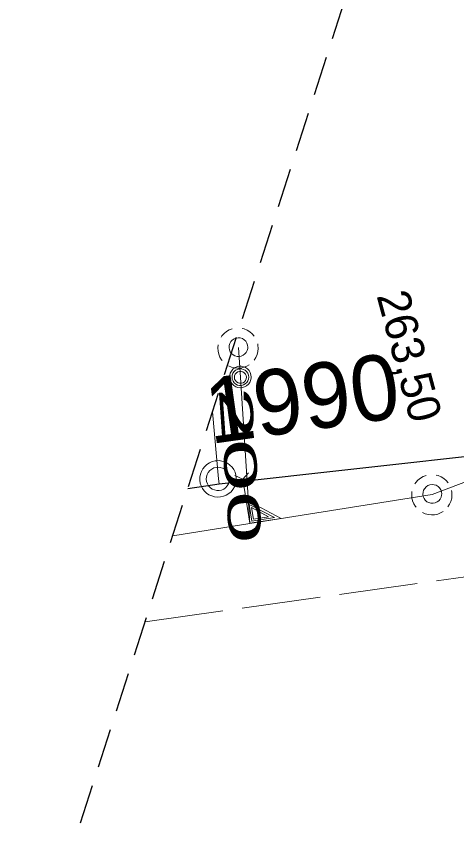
# Model space of a CAD drawing. Extents: x -732074 to -731966, y -1048695 to -1047982.
# Drawn here: x -732050.16 to -732039.39, y -1048256.3 to -1048236.39 of the extents above; entities that cross this region are included whole.
import ezdxf

# ---------------------------------------------------------------- set-up
doc = ezdxf.new("R2010")
doc.units = 0
doc.header["$LTSCALE"] = 0.32
doc.linetypes.add('LONG_DASHED', pattern=[7.5, 6, -1.5])
doc.linetypes.add('MEDIUM_DASHED', pattern=[4.5, 3, -1.5])
doc.layers.add('1', color=7, linetype='Continuous')
for name, color, linetype, lineweight in [('18', 7, 'Continuous', 13), ('20', 7, 'Continuous', 13), ('49', 7, 'Continuous', 13), ('63', 7, 'MEDIUM_DASHED', 25), ('8', 7, 'Continuous', 13)]:
    doc.layers.add(name, color=color, linetype=linetype, lineweight=lineweight)

msp = doc.modelspace()

# ---------------------------------------------------------------- linework, layer by layer
at = {"layer": '18'}
for p, q in [((-732044.481, -1048247.564), (-732044.77, -1048247.883)), ((-732044.814, -1048247.63), (-732044.409, -1048247.813))]:
    msp.add_line(p, q, dxfattribs=at)
for points in [[(-732044.883, -1048244.037), (-732044.954, -1048244.065), (-732045.021, -1048244.104), (-732045.081, -1048244.152), (-732045.132, -1048244.209), (-732045.156, -1048244.243)], [(-732044.342, -1048244.22), (-732044.392, -1048244.162), (-732044.45, -1048244.112), (-732044.515, -1048244.071), (-732044.586, -1048244.042), (-732044.635, -1048244.028)], [(-732045.228, -1048244.429), (-732045.233, -1048244.506), (-732045.228, -1048244.583), (-732045.212, -1048244.658), (-732045.183, -1048244.729), (-732045.142, -1048244.795), (-732045.127, -1048244.817)], [(-732044.347, -1048244.806), (-732044.306, -1048244.741), (-732044.275, -1048244.671), (-732044.255, -1048244.596), (-732044.248, -1048244.52), (-732044.253, -1048244.443), (-732044.259, -1048244.408)], [(-732044.97, -1048244.946), (-732044.9, -1048244.977), (-732044.825, -1048244.996), (-732044.749, -1048245.003), (-732044.672, -1048244.998), (-732044.597, -1048244.981), (-732044.525, -1048244.953), (-732044.465, -1048244.918)], [(-732044.62, -1048247.717), (-732044.447, -1048248.799), (-732043.686, -1048248.677), (-732044.538, -1048248.228)], [(-732040.142, -1048247.627), (-732040.213, -1048247.655), (-732040.279, -1048247.694), (-732040.34, -1048247.742), (-732040.391, -1048247.799), (-732040.414, -1048247.833)], [(-732039.6, -1048247.81), (-732039.651, -1048247.752), (-732039.708, -1048247.702), (-732039.774, -1048247.661), (-732039.845, -1048247.632), (-732039.894, -1048247.618)], [(-732040.487, -1048248.019), (-732040.492, -1048248.096), (-732040.487, -1048248.173), (-732040.47, -1048248.248), (-732040.441, -1048248.319), (-732040.401, -1048248.385), (-732040.386, -1048248.407)], [(-732039.605, -1048248.396), (-732039.565, -1048248.331), (-732039.534, -1048248.261), (-732039.514, -1048248.186), (-732039.507, -1048248.11), (-732039.512, -1048248.033), (-732039.517, -1048247.998)], [(-732044.469, -1048248.337), (-732044.404, -1048248.748), (-732043.846, -1048248.658), (-732044.469, -1048248.336)], [(-732044.41, -1048248.412), (-732044.364, -1048248.7), (-732043.997, -1048248.641), (-732044.411, -1048248.413)], [(-732040.228, -1048248.536), (-732040.159, -1048248.567), (-732040.083, -1048248.586), (-732040.007, -1048248.593), (-732039.931, -1048248.588), (-732039.855, -1048248.571), (-732039.784, -1048248.543), (-732039.723, -1048248.508)]]:
    msp.add_lwpolyline(points, dxfattribs=at)
for points in [[(-732044.499, -1048244.489), (-732044.505, -1048244.437), (-732044.522, -1048244.387), (-732044.551, -1048244.343), (-732044.589, -1048244.306), (-732044.634, -1048244.279), (-732044.684, -1048244.263), (-732044.736, -1048244.258), (-732044.788, -1048244.265), (-732044.837, -1048244.284), (-732044.88, -1048244.314), (-732044.916, -1048244.353), (-732044.942, -1048244.398), (-732044.956, -1048244.449), (-732044.96, -1048244.501), (-732044.951, -1048244.553), (-732044.931, -1048244.601), (-732044.901, -1048244.644), (-732044.861, -1048244.679), (-732044.815, -1048244.703), (-732044.764, -1048244.717), (-732044.712, -1048244.719), (-732044.66, -1048244.709), (-732044.612, -1048244.687), (-732044.57, -1048244.655), (-732044.537, -1048244.615), (-732044.513, -1048244.568), (-732044.5, -1048244.517)], [(-732044.418, -1048245.219), (-732044.424, -1048245.163), (-732044.441, -1048245.11), (-732044.47, -1048245.061), (-732044.508, -1048245.02), (-732044.554, -1048244.988), (-732044.606, -1048244.966), (-732044.661, -1048244.955), (-732044.717, -1048244.957), (-732044.772, -1048244.97), (-732044.823, -1048244.995), (-732044.867, -1048245.03), (-732044.903, -1048245.073), (-732044.928, -1048245.123), (-732044.943, -1048245.178), (-732044.946, -1048245.234), (-732044.937, -1048245.289), (-732044.916, -1048245.342), (-732044.885, -1048245.388), (-732044.845, -1048245.427), (-732044.797, -1048245.457), (-732044.744, -1048245.476), (-732044.688, -1048245.483), (-732044.632, -1048245.479), (-732044.578, -1048245.462), (-732044.529, -1048245.435), (-732044.487, -1048245.397), (-732044.454, -1048245.352), (-732044.431, -1048245.301), (-732044.419, -1048245.246)], [(-732044.477, -1048245.222), (-732044.483, -1048245.173), (-732044.501, -1048245.127), (-732044.529, -1048245.086), (-732044.566, -1048245.053), (-732044.61, -1048245.031), (-732044.658, -1048245.019), (-732044.707, -1048245.019), (-732044.755, -1048245.031), (-732044.799, -1048245.054), (-732044.836, -1048245.087), (-732044.864, -1048245.128), (-732044.881, -1048245.175), (-732044.887, -1048245.224), (-732044.88, -1048245.273), (-732044.862, -1048245.319), (-732044.834, -1048245.359), (-732044.797, -1048245.392), (-732044.753, -1048245.414), (-732044.704, -1048245.426), (-732044.655, -1048245.425), (-732044.607, -1048245.413), (-732044.564, -1048245.389), (-732044.527, -1048245.356), (-732044.499, -1048245.315), (-732044.483, -1048245.268)], [(-732044.536, -1048245.226), (-732044.542, -1048245.184), (-732044.559, -1048245.146), (-732044.587, -1048245.115), (-732044.622, -1048245.092), (-732044.662, -1048245.081), (-732044.704, -1048245.081), (-732044.744, -1048245.093), (-732044.779, -1048245.116), (-732044.806, -1048245.148), (-732044.823, -1048245.186), (-732044.828, -1048245.227), (-732044.822, -1048245.269), (-732044.804, -1048245.306), (-732044.776, -1048245.338), (-732044.74, -1048245.36), (-732044.7, -1048245.371), (-732044.658, -1048245.37), (-732044.618, -1048245.357), (-732044.584, -1048245.334), (-732044.557, -1048245.301), (-732044.541, -1048245.263)], [(-732039.757, -1048248.079), (-732039.764, -1048248.027), (-732039.781, -1048247.977), (-732039.809, -1048247.933), (-732039.848, -1048247.896), (-732039.892, -1048247.869), (-732039.943, -1048247.853), (-732039.995, -1048247.848), (-732040.046, -1048247.855), (-732040.095, -1048247.874), (-732040.139, -1048247.904), (-732040.174, -1048247.943), (-732040.201, -1048247.988), (-732040.215, -1048248.039), (-732040.218, -1048248.091), (-732040.21, -1048248.143), (-732040.19, -1048248.191), (-732040.159, -1048248.234), (-732040.12, -1048248.269), (-732040.073, -1048248.293), (-732040.022, -1048248.307), (-732039.97, -1048248.309), (-732039.919, -1048248.299), (-732039.87, -1048248.277), (-732039.828, -1048248.245), (-732039.796, -1048248.205), (-732039.772, -1048248.158), (-732039.759, -1048248.107)]]:
    msp.add_lwpolyline(points, close=True, dxfattribs=at)
at = {"layer": '20'}
msp.add_line((-732039.989, -1048248.09), (-732027.55, -1048243.38), dxfattribs=at)
msp.add_line((-732039.989, -1048248.09), (-732027.55, -1048243.38), dxfattribs=at)
at = {"layer": '20', "linetype": 'LONG_DASHED'}
msp.add_line((-732047.012, -1048251.212), (-732038.07, -1048249.95), dxfattribs=at)
msp.add_line((-732047.012, -1048251.212), (-732038.07, -1048249.95), dxfattribs=at)
at = {"layer": '20'}
msp.add_lwpolyline([(-732046.335, -1048249.103), (-732044.453, -1048248.803), (-732039.989, -1048248.09)], dxfattribs=at)
msp.add_lwpolyline([(-732046.335, -1048249.103), (-732044.453, -1048248.803), (-732039.989, -1048248.09)], dxfattribs=at)
at = {"layer": '49'}
msp.add_lwpolyline([(-732044.73, -1048244.5), (-732044.682, -1048245.232), (-732044.453, -1048248.803)], dxfattribs=at)
msp.add_lwpolyline([(-732044.73, -1048244.5), (-732044.682, -1048245.232), (-732044.453, -1048248.803)], dxfattribs=at)
at = {"layer": '63'}
msp.add_lwpolyline([(-732073.996, -1048412.713), (-732069.268, -1048320.574), (-732069.268, -1048320.571), (-732031.703, -1048203.502)], dxfattribs=at)
at = {"layer": '8'}
for p, q in [((-732045.219, -1048247.71), (-732045.363, -1048246.072)), ((-732045.199, -1048247.83), (-732045.219, -1048247.71))]:
    msp.add_line(p, q, dxfattribs=at)
at = {"layer": '8', "lineweight": 25}
msp.add_lwpolyline([(-732045.964, -1048247.947), (-732045.199, -1048247.83), (-732034.949, -1048246.69), (-732033.82, -1048241.31)], dxfattribs=at)
at = {"layer": '8'}
for points in [[(-732045.302, -1048247.27), (-732045.373, -1048247.288), (-732045.44, -1048247.318), (-732045.502, -1048247.357), (-732045.555, -1048247.407), (-732045.602, -1048247.464), (-732045.637, -1048247.528), (-732045.661, -1048247.597), (-732045.674, -1048247.669), (-732045.675, -1048247.742), (-732045.664, -1048247.815), (-732045.641, -1048247.884), (-732045.607, -1048247.95), (-732045.564, -1048248.007), (-732045.511, -1048248.058), (-732045.45, -1048248.1), (-732045.384, -1048248.13), (-732045.313, -1048248.15), (-732045.241, -1048248.158), (-732045.167, -1048248.154), (-732045.096, -1048248.138), (-732045.028, -1048248.111), (-732044.966, -1048248.073), (-732044.91, -1048248.025), (-732044.864, -1048247.969), (-732044.826, -1048247.906), (-732044.8, -1048247.837), (-732044.785, -1048247.766), (-732044.782, -1048247.692), (-732044.791, -1048247.62), (-732044.812, -1048247.549), (-732044.844, -1048247.484), (-732044.886, -1048247.424), (-732044.938, -1048247.372), (-732044.997, -1048247.329), (-732045.063, -1048247.296), (-732045.132, -1048247.274), (-732045.205, -1048247.265), (-732045.278, -1048247.267)], [(-732045.276, -1048247.429), (-732045.332, -1048247.445), (-732045.384, -1048247.472), (-732045.43, -1048247.508), (-732045.467, -1048247.553), (-732045.495, -1048247.605), (-732045.511, -1048247.661), (-732045.515, -1048247.719), (-732045.508, -1048247.778), (-732045.488, -1048247.833), (-732045.458, -1048247.883), (-732045.418, -1048247.926), (-732045.371, -1048247.96), (-732045.317, -1048247.983), (-732045.259, -1048247.996), (-732045.202, -1048247.997), (-732045.144, -1048247.985), (-732045.09, -1048247.962), (-732045.042, -1048247.928), (-732045.002, -1048247.885), (-732044.971, -1048247.836), (-732044.952, -1048247.781), (-732044.943, -1048247.722), (-732044.947, -1048247.664), (-732044.962, -1048247.608), (-732044.988, -1048247.556), (-732045.025, -1048247.51), (-732045.071, -1048247.473), (-732045.122, -1048247.446), (-732045.178, -1048247.43), (-732045.237, -1048247.426)]]:
    msp.add_lwpolyline(points, close=True, dxfattribs=at)

# ---------------------------------------------------------------- texts
at = {"layer": '1'}
for s, height, rotation, p in [('263,50', 0.8, 285, (-732041.355, -1048243.224)), ('1990', 1.6, 8, (-732045.42, -1048246.86))]:
    msp.add_text(s, height=height, rotation=rotation, dxfattribs=at).set_placement(p)
at = {"layer": '1', "width": 2.15}
msp.add_text('200 ', height=0.8, rotation=274, dxfattribs=at).set_placement((-732045.214, -1048245.488))

doc.saveas('drawing.dxf')
